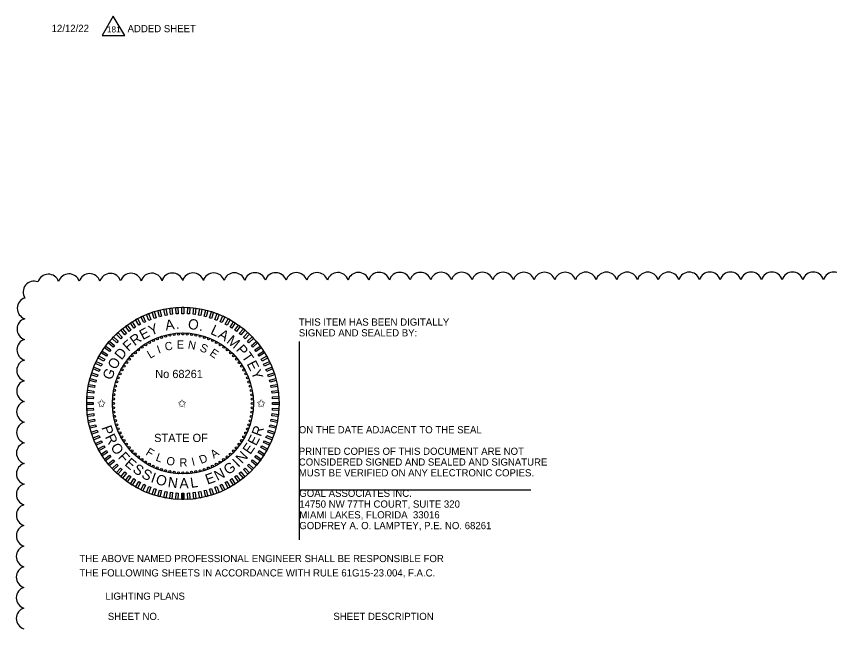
# Model space of a CAD drawing. Extents: x -811.2 to -795, y -2307.6 to -2235.1.
# Drawn here: x -811.11 to -803.18, y -2263.37 to -2257.4 of the extents above; entities that cross this region are included whole.
import ezdxf

# ---------------------------------------------------------------- set-up
doc = ezdxf.new("R2010")
doc.units = 0
for name, color, linetype in [('AdhocPoint_dp', 7, 'Continuous'), ('Cloud_dp', 7, 'Continuous'), ('Logo_dp', 7, 'Continuous'), ('TeleMisc', 7, 'Continuous'), ('TextDetails', 7, 'Continuous'), ('TextMinor', 7, 'Continuous'), ('TextMisc', 7, 'Continuous')]:
    doc.layers.add(name, color=color, linetype=linetype)

msp = doc.modelspace()

# ---------------------------------------------------------------- linework, layer by layer
at = {"layer": 'AdhocPoint_dp'}
for p, q in [((-808.3546, -2260.5734), (-808.3546, -2262.5081)), ((-808.3546, -2262.0181), (-806.0979, -2262.0181))]:
    msp.add_line(p, q, dxfattribs=at)
at = {"layer": 'Cloud_dp'}
msp.add_lwpolyline([(-810.1682, -2257.4017), (-810.2759, -2257.5898), (-810.0553, -2257.5898)], close=True, dxfattribs=at)
for centre, start, end in [((-810.8012, -2260.0225), 18.59454, 163.59454), ((-810.5999, -2260.0193), 18.21421, 163.21421), ((-810.3985, -2260.0171), 18.04696, 163.04696), ((-810.197, -2260.0154), 17.94666, 162.94666), ((-809.9955, -2260.0139), 17.87787, 162.87787), ((-809.7939, -2260.0127), 17.82689, 162.82689), ((-809.5924, -2260.0116), 17.78716, 162.78716), ((-809.3909, -2260.0107), 17.75505, 162.75505), ((-809.1894, -2260.0098), 17.72841, 162.72841), ((-808.9878, -2260.009), 17.70584, 162.70584), ((-808.7863, -2260.0084), 17.6864, 162.6864), ((-808.5848, -2260.0077), 17.66942, 162.66942), ((-808.3832, -2260.0072), 17.65443, 162.65443), ((-808.1817, -2260.0066), 17.64106, 162.64106), ((-807.9801, -2260.0062), 17.62905, 162.62905), ((-807.7786, -2260.0057), 17.61817, 162.61817), ((-807.577, -2260.0053), 17.60826, 162.60826), ((-807.3755, -2260.005), 17.59919, 162.59919), ((-807.174, -2260.0046), 17.59084, 162.59084), ((-806.9724, -2260.0043), 17.58312, 162.58312), ((-806.7709, -2260.004), 17.57595, 162.57595), ((-806.5693, -2260.0038), 17.56928, 162.56928), ((-806.3678, -2260.0036), 17.56305, 162.56305), ((-806.1662, -2260.0033), 17.55721, 162.55721), ((-805.9647, -2260.0032), 17.55172, 162.55172), ((-805.7631, -2260.003), 17.54655, 162.54655), ((-805.5616, -2260.0028), 17.54167, 162.54167), ((-805.3601, -2260.0027), 17.53705, 162.53705), ((-805.1585, -2260.0026), 17.53267, 162.53267), ((-804.957, -2260.0025), 17.52851, 162.52851), ((-804.7554, -2260.0024), 17.52455, 162.52455), ((-804.5539, -2260.0023), 17.52079, 162.52079), ((-804.3523, -2260.0022), 17.51719, 162.51719), ((-804.1508, -2260.0022), 17.51375, 162.51375), ((-803.9492, -2260.0021), 17.51046, 162.51046), ((-803.7477, -2260.0021), 17.50731, 162.50731), ((-803.5461, -2260.0021), 17.50428, 162.50428), ((-803.3446, -2260.0021), 17.50138, 162.50138), ((-803.143, -2260.0021), 17.5, 162.5), ((-810.9414, -2260.0909), 68.43954, 213.43954), ((-810.999, -2260.2503), 106.80445, 251.80445), ((-811.001, -2260.4517), 107.04367, 252.04367), ((-811.0025, -2260.6532), 107.15618, 252.15618), ((-811.0035, -2260.8547), 107.22533, 252.22533), ((-811.0044, -2261.0562), 107.27338, 252.27338), ((-811.0052, -2261.2578), 107.30928, 252.30928), ((-811.0058, -2261.4593), 107.33743, 252.33743), ((-811.0063, -2261.6608), 107.36027, 252.36027), ((-811.0068, -2261.8624), 107.37928, 252.37928), ((-811.0072, -2262.0639), 107.39543, 252.39543), ((-811.0075, -2262.2655), 107.40937, 252.40937), ((-811.0078, -2262.467), 107.42156, 252.42156), ((-811.0081, -2262.6685), 107.43234, 252.43234), ((-811.0083, -2262.8701), 107.44197, 252.44197), ((-811.0085, -2263.0716), 107.45063, 252.45063), ((-811.0086, -2263.2732), 107.45847, 252.45847)]:
    msp.add_arc(centre, 0.1057, start, end, dxfattribs=at)
at = {"layer": 'TextDetails'}
for radius in [0.9375, 0.6875]:
    msp.add_circle((-809.4901, -2261.1768), radius, dxfattribs=at)
at = {"layer": 'TextMisc'}
for p, q in [((-809.5001, -2262.1144), (-809.5003, -2262.0519)), ((-809.4901, -2262.1143), (-809.4903, -2262.0518)), ((-809.4801, -2262.1143), (-809.4803, -2262.0518))]:
    msp.add_line(p, q, dxfattribs=at)
for points in [[(-809.6441, -2260.3154), (-809.6639, -2260.3192), (-809.6756, -2260.2578), (-809.6558, -2260.2541)], [(-809.5897, -2260.3074), (-809.6097, -2260.31), (-809.6175, -2260.248), (-809.5975, -2260.2455)], [(-809.5349, -2260.3029), (-809.555, -2260.3042), (-809.559, -2260.2418), (-809.5388, -2260.2406)], [(-809.4799, -2260.3018), (-809.5001, -2260.3018), (-809.5001, -2260.2394), (-809.4799, -2260.2394)], [(-809.425, -2260.3042), (-809.4452, -2260.3029), (-809.4412, -2260.2406), (-809.4211, -2260.2419)], [(-809.3703, -2260.31), (-809.3904, -2260.3075), (-809.3825, -2260.2455), (-809.3625, -2260.248)], [(-809.3161, -2260.3192), (-809.336, -2260.3154), (-809.3243, -2260.2541), (-809.3044, -2260.2579)], [(-809.8535, -2260.3808), (-809.8717, -2260.3893), (-809.8983, -2260.3329), (-809.8801, -2260.3243)], [(-809.8028, -2260.3595), (-809.8215, -2260.3669), (-809.8445, -2260.3089), (-809.8258, -2260.3015)], [(-809.7508, -2260.3415), (-809.77, -2260.3477), (-809.7893, -2260.2883), (-809.7701, -2260.2821)], [(-809.6979, -2260.3268), (-809.7174, -2260.3318), (-809.7329, -2260.2713), (-809.7134, -2260.2663)], [(-809.2626, -2260.3318), (-809.2822, -2260.3268), (-809.2667, -2260.2663), (-809.2471, -2260.2714)], [(-809.21, -2260.3478), (-809.2292, -2260.3415), (-809.2099, -2260.2822), (-809.1907, -2260.2884)], [(-809.1585, -2260.367), (-809.1773, -2260.3596), (-809.1543, -2260.3015), (-809.1355, -2260.309)], [(-809.1083, -2260.3894), (-809.1266, -2260.3808), (-809.1, -2260.3243), (-809.0817, -2260.3329)], [(-809.9962, -2260.4629), (-810.0125, -2260.4748), (-810.0492, -2260.4243), (-810.0329, -2260.4124)], [(-809.9504, -2260.4326), (-809.9674, -2260.4434), (-810.0009, -2260.3907), (-809.9838, -2260.3799)], [(-809.9027, -2260.4051), (-809.9204, -2260.4149), (-809.9505, -2260.3601), (-809.9328, -2260.3504)], [(-809.0596, -2260.415), (-809.0773, -2260.4052), (-809.0473, -2260.3505), (-809.0296, -2260.3602)], [(-809.0127, -2260.4435), (-809.0297, -2260.4327), (-808.9962, -2260.38), (-808.9792, -2260.3908)], [(-808.9675, -2260.4749), (-808.9839, -2260.463), (-808.9472, -2260.4125), (-808.9308, -2260.4244)], [(-810.0817, -2260.532), (-810.0964, -2260.5458), (-810.1391, -2260.5003), (-810.1244, -2260.4865)], [(-810.04, -2260.4961), (-810.0556, -2260.509), (-810.0954, -2260.4609), (-810.0798, -2260.448)], [(-808.9245, -2260.5091), (-808.9401, -2260.4962), (-808.9003, -2260.4481), (-808.8847, -2260.461)], [(-808.8837, -2260.5459), (-808.8984, -2260.5321), (-808.8557, -2260.4866), (-808.8409, -2260.5004)], [(-810.1578, -2260.6112), (-810.1707, -2260.6268), (-810.2188, -2260.587), (-810.206, -2260.5714)], [(-810.121, -2260.5704), (-810.1348, -2260.5851), (-810.1803, -2260.5424), (-810.1665, -2260.5277)], [(-808.8453, -2260.5853), (-808.8591, -2260.5706), (-808.8136, -2260.5278), (-808.7998, -2260.5425)], [(-808.8094, -2260.6269), (-808.8223, -2260.6114), (-808.7742, -2260.5716), (-808.7613, -2260.5871)], [(-810.192, -2260.6543), (-810.2039, -2260.6706), (-810.2544, -2260.6339), (-810.2426, -2260.6176)], [(-808.7762, -2260.6708), (-808.7881, -2260.6544), (-808.7376, -2260.6177), (-808.7257, -2260.6341)], [(-810.252, -2260.7464), (-810.2617, -2260.7641), (-810.3164, -2260.734), (-810.3067, -2260.7163)], [(-810.2235, -2260.6994), (-810.2343, -2260.7164), (-810.287, -2260.683), (-810.2762, -2260.6659)], [(-808.7458, -2260.7166), (-808.7567, -2260.6995), (-808.7039, -2260.6661), (-808.6931, -2260.6831)], [(-808.7184, -2260.7642), (-808.7281, -2260.7465), (-808.6734, -2260.7164), (-808.6637, -2260.7341)], [(-810.2775, -2260.7951), (-810.2861, -2260.8133), (-810.3426, -2260.7867), (-810.334, -2260.7685)], [(-808.694, -2260.8135), (-808.7026, -2260.7952), (-808.6461, -2260.7686), (-808.6375, -2260.7869)], [(-810.3192, -2260.8968), (-810.3254, -2260.916), (-810.3848, -2260.8967), (-810.3786, -2260.8775)], [(-810.3, -2260.8453), (-810.3074, -2260.864), (-810.3654, -2260.841), (-810.358, -2260.8223)], [(-808.6728, -2260.8642), (-808.6802, -2260.8454), (-808.6222, -2260.8224), (-808.6147, -2260.8412)], [(-808.6548, -2260.9161), (-808.661, -2260.8969), (-808.6016, -2260.8776), (-808.5954, -2260.8968)], [(-810.3351, -2260.9494), (-810.3401, -2260.9689), (-810.4006, -2260.9534), (-810.3956, -2260.9338)], [(-808.64, -2260.9691), (-808.6451, -2260.9495), (-808.5846, -2260.934), (-808.5796, -2260.9536)], [(-810.357, -2261.0571), (-810.3595, -2261.0771), (-810.4214, -2261.0693), (-810.4189, -2261.0492)], [(-810.3477, -2261.0029), (-810.3515, -2261.0227), (-810.4129, -2261.011), (-810.4091, -2260.9912)], [(-808.6287, -2261.0229), (-808.6325, -2261.0031), (-808.5711, -2260.9914), (-808.5673, -2261.0112)], [(-808.6207, -2261.0773), (-808.6232, -2261.0572), (-808.5613, -2261.0494), (-808.5588, -2261.0695)], [(-810.3628, -2261.1117), (-810.364, -2261.1319), (-810.4264, -2261.128), (-810.4251, -2261.1078)], [(-808.6162, -2261.1321), (-808.6174, -2261.1119), (-808.5551, -2261.108), (-808.5539, -2261.1281)], [(-810.3651, -2261.1667), (-810.3651, -2261.1868), (-810.4276, -2261.1868), (-810.4276, -2261.1667)], [(-808.6151, -2261.187), (-808.6151, -2261.1668), (-808.5526, -2261.1668), (-808.5526, -2261.187)], [(-810.3641, -2261.2216), (-810.3628, -2261.2418), (-810.4251, -2261.2457), (-810.4264, -2261.2255)], [(-810.3595, -2261.2764), (-810.357, -2261.2964), (-810.4189, -2261.3043), (-810.4215, -2261.2842)], [(-808.6233, -2261.2966), (-808.6207, -2261.2766), (-808.5588, -2261.2844), (-808.5613, -2261.3044)], [(-808.6175, -2261.242), (-808.6162, -2261.2218), (-808.5539, -2261.2257), (-808.5551, -2261.2459)], [(-810.3516, -2261.3308), (-810.3478, -2261.3506), (-810.4091, -2261.3623), (-810.4129, -2261.3425)], [(-808.6325, -2261.3508), (-808.6287, -2261.331), (-808.5674, -2261.3427), (-808.5712, -2261.3625)], [(-810.3402, -2261.3846), (-810.3352, -2261.4041), (-810.3956, -2261.4197), (-810.4007, -2261.4001)], [(-810.3255, -2261.4376), (-810.3192, -2261.4568), (-810.3786, -2261.476), (-810.3849, -2261.4568)], [(-808.6611, -2261.4569), (-808.6548, -2261.4377), (-808.5954, -2261.457), (-808.6017, -2261.4762)], [(-808.6451, -2261.4043), (-808.6401, -2261.3848), (-808.5796, -2261.4003), (-808.5846, -2261.4198)], [(-810.3074, -2261.4895), (-810.3, -2261.5083), (-810.3581, -2261.5312), (-810.3655, -2261.5125)], [(-808.6803, -2261.5084), (-808.6729, -2261.4897), (-808.6148, -2261.5126), (-808.6222, -2261.5314)], [(-810.2862, -2261.5402), (-810.2776, -2261.5585), (-810.3341, -2261.585), (-810.3427, -2261.5668)], [(-810.2618, -2261.5895), (-810.2521, -2261.6072), (-810.3068, -2261.6372), (-810.3165, -2261.6195)], [(-808.7282, -2261.6073), (-808.7185, -2261.5896), (-808.6638, -2261.6197), (-808.6735, -2261.6374)], [(-808.7027, -2261.5586), (-808.6941, -2261.5404), (-808.6376, -2261.5669), (-808.6462, -2261.5852)], [(-810.2344, -2261.6371), (-810.2236, -2261.6541), (-810.2763, -2261.6876), (-810.2871, -2261.6706)], [(-810.204, -2261.6829), (-810.1922, -2261.6993), (-810.2427, -2261.736), (-810.2545, -2261.7196)], [(-808.7882, -2261.6994), (-808.7763, -2261.6831), (-808.7258, -2261.7198), (-808.7377, -2261.7361)], [(-808.7568, -2261.6543), (-808.7459, -2261.6373), (-808.6932, -2261.6707), (-808.704, -2261.6878)], [(-810.1708, -2261.7268), (-810.158, -2261.7423), (-810.2061, -2261.7821), (-810.2189, -2261.7666)], [(-808.8224, -2261.7425), (-808.8095, -2261.7269), (-808.7614, -2261.7667), (-808.7743, -2261.7823)], [(-810.135, -2261.7684), (-810.1211, -2261.7831), (-810.1667, -2261.8259), (-810.1805, -2261.8112)], [(-810.0965, -2261.8077), (-810.0818, -2261.8216), (-810.1246, -2261.8671), (-810.1393, -2261.8533)], [(-810.0557, -2261.8446), (-810.0402, -2261.8574), (-810.08, -2261.9055), (-810.0955, -2261.8927)], [(-808.9402, -2261.8576), (-808.9246, -2261.8447), (-808.8848, -2261.8928), (-808.9004, -2261.9057)], [(-808.8985, -2261.8217), (-808.8838, -2261.8079), (-808.8411, -2261.8534), (-808.8558, -2261.8672)], [(-808.8592, -2261.7833), (-808.8454, -2261.7686), (-808.7999, -2261.8113), (-808.8137, -2261.826)], [(-810.0127, -2261.8788), (-809.9964, -2261.8906), (-810.0331, -2261.9411), (-810.0494, -2261.9293)], [(-809.9676, -2261.9102), (-809.9505, -2261.921), (-809.984, -2261.9737), (-810.001, -2261.9629)], [(-809.0299, -2261.9211), (-809.0128, -2261.9103), (-808.9794, -2261.963), (-808.9964, -2261.9738)], [(-808.984, -2261.8907), (-808.9677, -2261.8789), (-808.931, -2261.9294), (-808.9473, -2261.9413)], [(-809.9206, -2261.9387), (-809.9029, -2261.9485), (-809.933, -2262.0032), (-809.9507, -2261.9934)], [(-809.8719, -2261.9643), (-809.8536, -2261.9728), (-809.8802, -2262.0293), (-809.8985, -2262.0208)], [(-809.8217, -2261.9867), (-809.8029, -2261.9941), (-809.8259, -2262.0522), (-809.8447, -2262.0447)], [(-809.1775, -2261.9942), (-809.1587, -2261.9867), (-809.1357, -2262.0448), (-809.1545, -2262.0522)], [(-809.1268, -2261.9729), (-809.1085, -2261.9643), (-809.0819, -2262.0208), (-809.1002, -2262.0294)], [(-809.0775, -2261.9485), (-809.0598, -2261.9388), (-809.0297, -2261.9935), (-809.0474, -2262.0033)], [(-809.7702, -2262.0059), (-809.751, -2262.0121), (-809.7703, -2262.0715), (-809.7895, -2262.0653)], [(-809.7176, -2262.0218), (-809.698, -2262.0269), (-809.7136, -2262.0873), (-809.7331, -2262.0823)], [(-809.6641, -2262.0345), (-809.6443, -2262.0382), (-809.656, -2262.0996), (-809.6758, -2262.0958)], [(-809.6099, -2262.0437), (-809.5899, -2262.0462), (-809.5977, -2262.1082), (-809.6177, -2262.1056)], [(-809.5552, -2262.0495), (-809.5351, -2262.0508), (-809.539, -2262.1131), (-809.5591, -2262.1118)], [(-809.5003, -2262.0519), (-809.4801, -2262.0519), (-809.4801, -2262.1143), (-809.5003, -2262.1143)], [(-809.4453, -2262.0508), (-809.4252, -2262.0495), (-809.4213, -2262.1118), (-809.4414, -2262.1131)], [(-809.3906, -2262.0462), (-809.3705, -2262.0437), (-809.3627, -2262.1057), (-809.3827, -2262.1082)], [(-809.3362, -2262.0383), (-809.3163, -2262.0345), (-809.3046, -2262.0958), (-809.3245, -2262.0996)], [(-809.2824, -2262.0269), (-809.2628, -2262.0219), (-809.2473, -2262.0824), (-809.2668, -2262.0874)], [(-809.2294, -2262.0122), (-809.2102, -2262.006), (-809.1909, -2262.0653), (-809.2101, -2262.0716)]]:
    msp.add_lwpolyline(points, close=True, dxfattribs=at)
for centre in [(-809.5745, -2260.5046), (-809.5321, -2260.5007), (-809.4896, -2260.4994), (-809.447, -2260.5007), (-809.4046, -2260.5048), (-809.816, -2260.5829), (-809.7781, -2260.5636), (-809.739, -2260.5467), (-809.6989, -2260.5324), (-809.6581, -2260.5205), (-809.6165, -2260.5113), (-809.3626, -2260.5115), (-809.3211, -2260.5208), (-809.2802, -2260.5327), (-809.2402, -2260.5472), (-809.2012, -2260.5641), (-809.1633, -2260.5834), (-809.9215, -2260.6545), (-809.8879, -2260.6284), (-809.8526, -2260.6045), (-809.1266, -2260.6051), (-809.0915, -2260.6291), (-809.0578, -2260.6552), (-810.0118, -2260.7446), (-809.9836, -2260.7127), (-809.9535, -2260.6826), (-809.0259, -2260.6834), (-808.9959, -2260.7135), (-808.9678, -2260.7454), (-810.0618, -2260.8134), (-810.0379, -2260.7782), (-808.9417, -2260.7791), (-808.9178, -2260.8143), (-810.1029, -2260.8879), (-810.0835, -2260.85), (-808.8962, -2260.851), (-808.8769, -2260.8889), (-810.1343, -2260.967), (-810.1198, -2260.9269), (-808.86, -2260.928), (-808.8456, -2260.968), (-810.1555, -2261.0493), (-810.1462, -2261.0078), (-808.8338, -2261.0089), (-808.8245, -2261.0504), (-810.1662, -2261.1337), (-810.1622, -2261.0914), (-808.8179, -2261.0925), (-808.814, -2261.1349), (-810.1676, -2261.1763), (-810.1663, -2261.2188), (-808.814, -2261.2199), (-808.8126, -2261.1774), (-810.1623, -2261.2612), (-808.8181, -2261.2623), (-810.1557, -2261.3032), (-810.1464, -2261.3448), (-808.8341, -2261.3459), (-808.8248, -2261.3043), (-810.1346, -2261.3857), (-810.1202, -2261.4257), (-808.8604, -2261.4268), (-808.846, -2261.3867), (-810.1033, -2261.4648), (-810.0841, -2261.5027), (-810.0624, -2261.5394), (-808.8967, -2261.5037), (-808.8774, -2261.4658), (-810.0385, -2261.5746), (-810.0125, -2261.6082), (-808.9685, -2261.6091), (-808.9424, -2261.5755), (-808.9184, -2261.5403), (-809.9844, -2261.6402), (-809.9543, -2261.6703), (-809.0268, -2261.6711), (-808.9967, -2261.641), (-809.9224, -2261.6985), (-809.8888, -2261.7246), (-809.8536, -2261.7485), (-809.817, -2261.7702), (-809.1642, -2261.7708), (-809.1276, -2261.7491), (-809.0924, -2261.7253), (-809.0587, -2261.6992), (-809.7791, -2261.7896), (-809.74, -2261.8065), (-809.7, -2261.821), (-809.6591, -2261.8329), (-809.6176, -2261.8422), (-809.5756, -2261.8489), (-809.5332, -2261.8529), (-809.4901, -2261.8543), (-809.4481, -2261.853), (-809.4058, -2261.849), (-809.3637, -2261.8424), (-809.3222, -2261.8332), (-809.2813, -2261.8213), (-809.2412, -2261.8069), (-809.2022, -2261.7901)]:
    msp.add_circle(centre, 0.01, dxfattribs=at)

# ---------------------------------------------------------------- texts
at = {"layer": 'Cloud_dp'}
msp.add_text('181', height=0.05998, rotation=0, dxfattribs=at).set_placement((-810.2304, -2257.5596))
at = {"layer": 'Logo_dp'}
for s, p in [('THIS ITEM HAS BEEN DIGITALLY', (-808.3596, -2260.4183)), ('SIGNED AND SEALED BY:', (-808.3596, -2260.5233)), ('ON THE DATE ADJACENT TO THE SEAL', (-808.3596, -2261.4683)), ('PRINTED COPIES OF THIS DOCUMENT ARE NOT ', (-808.3596, -2261.6783)), ('CONSIDERED SIGNED AND SEALED AND SIGNATURE ', (-808.3596, -2261.7833)), ('MUST BE VERIFIED ON ANY ELECTRONIC COPIES.', (-808.3596, -2261.8883)), ('GOAL ASSOCIATES INC.', (-808.3546, -2262.0881)), ('14750 NW 77TH COURT, SUITE 320', (-808.3546, -2262.1931)), ('MIAMI LAKES, FLORIDA  33016', (-808.3546, -2262.2981)), ('GODFREY A. O. LAMPTEY, P.E. NO. 68261', (-808.3546, -2262.4031)), ('THE ABOVE NAMED PROFESSIONAL ENGINEER SHALL BE RESPONSIBLE FOR ', (-810.4987, -2262.7243)), ('THE FOLLOWING SHEETS IN ACCORDANCE WITH RULE 61G15-23.004, F.A.C.', (-810.4987, -2262.8643)), ('LIGHTING PLANS', (-810.245, -2263.0913))]:
    msp.add_text(s, height=0.07, dxfattribs=at).set_placement(p)
at = {"layer": 'TeleMisc'}
for s, p in [('SHEET NO.', (-810.2215, -2263.2883)), ('SHEET DESCRIPTION', (-808.0226, -2263.2883))]:
    msp.add_text(s, height=0.07, dxfattribs=at).set_placement(p)
at = {"layer": 'TextMinor'}
for s, p in [('12/12/22', (-810.7698, -2257.5548)), ('ADDED SHEET', (-810.0291, -2257.5572))]:
    msp.add_text(s, height=0.07, dxfattribs=at).set_placement(p)
at = {"layer": 'TextMisc'}
for s, height, rotation, p in [('Y', 0.1, 21.06329, (-809.8021, -2260.5174)), ('A', 0.1, 8.80884, (-809.6551, -2260.4662)), ('O', 0.1, 352.18771, (-809.4449, -2260.4487)), ('L', 0.1, 334.67271, (-809.2279, -2260.4961)), ('R', 0.1, 35.92688, (-809.9609, -2260.6195)), ('E', 0.1, 28.10553, (-809.8806, -2260.5607)), ('.', 0.1, 1.04184, (-809.5575, -2260.4504)), ('.', 0.1, 343.52684, (-809.3358, -2260.4638)), ('A', 0.1, 328.40959, (-809.1552, -2260.5288)), ('F', 0.1, 42.37723, (-810.0205, -2260.6759)), ('C', 0.08, 12.20255, (-809.6579, -2260.6652)), ('E', 0.08, 0.41861, (-809.5498, -2260.6418)), ('N', 0.08, 349.29143, (-809.4455, -2260.6403)), ('M', 0.1, 320.6426, (-809.0707, -2260.58)), ('D', 0.1, 50.8569, (-810.0885, -2260.7596)), ('I', 0.08, 20.01168, (-809.7258, -2260.6928)), ('S', 0.08, 337.02207, (-809.3325, -2260.662)), ('E', 0.08, 325.86633, (-809.2358, -2260.7023)), ('P', 0.1, 311.19658, (-808.9784, -2260.6569)), ('O', 0.1, 59.51777, (-810.1446, -2260.8545)), ('L', 0.08, 30.40215, (-809.8093, -2260.7432)), ('T', 0.1, 304.45632, (-808.9209, -2260.7206)), ('E', 0.1, 297.63152, (-808.8707, -2260.7914)), ('G', 0.1, 68.0518, (-810.1851, -2260.9552)), ('Y', 0.1, 290.58928, (-808.8281, -2260.8703)), ('P', 0.1, 289.40551, (-810.2848, -2261.4114)), ('R', 0.1, 69.5134, (-808.7299, -2261.5065)), ('R', 0.1, 296.14576, (-810.2518, -2261.5031)), ('E', 0.1, 62.47116, (-808.7761, -2261.5973)), ('O', 0.1, 303.96711, (-810.2003, -2261.6037)), ('E', 0.1, 55.42892, (-808.833, -2261.6816)), ('F', 0.1, 312.62798, (-810.1279, -2261.7058)), ('F', 0.08, 328.72408, (-809.8582, -2261.6734)), ('L', 0.08, 339.29159, (-809.7609, -2261.7325)), ('D', 0.08, 22.01279, (-809.312, -2261.7687)), ('A', 0.08, 34.49917, (-809.1883, -2261.7162)), ('N', 0.1, 47.17876, (-808.9123, -2261.7707)), ('E', 0.1, 319.07833, (-810.0645, -2261.7741)), ('O', 0.08, 349.68206, (-809.6562, -2261.7722)), ('R', 0.08, 2.33977, (-809.5217, -2261.7941)), ('I', 0.08, 14.20366, (-809.3941, -2261.7875)), ('G', 0.1, 35.11153, (-809.0492, -2261.8784)), ('I', 0.1, 43.64556, (-808.9499, -2261.8052)), ('S', 0.1, 326.12056, (-809.9869, -2261.84)), ('S', 0.1, 333.193, (-809.9015, -2261.8961)), ('N', 0.1, 26.86136, (-809.1544, -2261.9344)), ('I', 0.1, 340.26543, (-809.8098, -2261.9413)), ('O', 0.1, 343.79863, (-809.7621, -2261.9595)), ('N', 0.1, 352.45949, (-809.6411, -2261.9916)), ('A', 0.1, 0.70966, (-809.5227, -2262.0048)), ('L', 0.1, 8.47665, (-809.4105, -2262.0016)), ('E', 0.1, 19.81912, (-809.2498, -2261.9698))]:
    msp.add_text(s, height=height, rotation=rotation, dxfattribs=at).set_placement(p)
for s, p in [('No 68261', (-809.7591, -2260.9296)), ('✩', (-810.3251, -2261.2148)), ('✩', (-809.5404, -2261.2148)), ('✩', (-808.7685, -2261.2148)), ('STATE OF', (-809.7698, -2261.553))]:
    msp.add_text(s, height=0.08, dxfattribs=at).set_placement(p)

doc.saveas('drawing.dxf')
